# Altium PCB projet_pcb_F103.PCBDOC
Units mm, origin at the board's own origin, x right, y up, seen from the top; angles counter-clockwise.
Board outline 90.04 x 70.1 mm, 2 copper layers (TopLayer, BottomLayer); 62 components, 54 nets, 254 pads, 0 vias.
Unrouted connection lines stored in the file: 158.
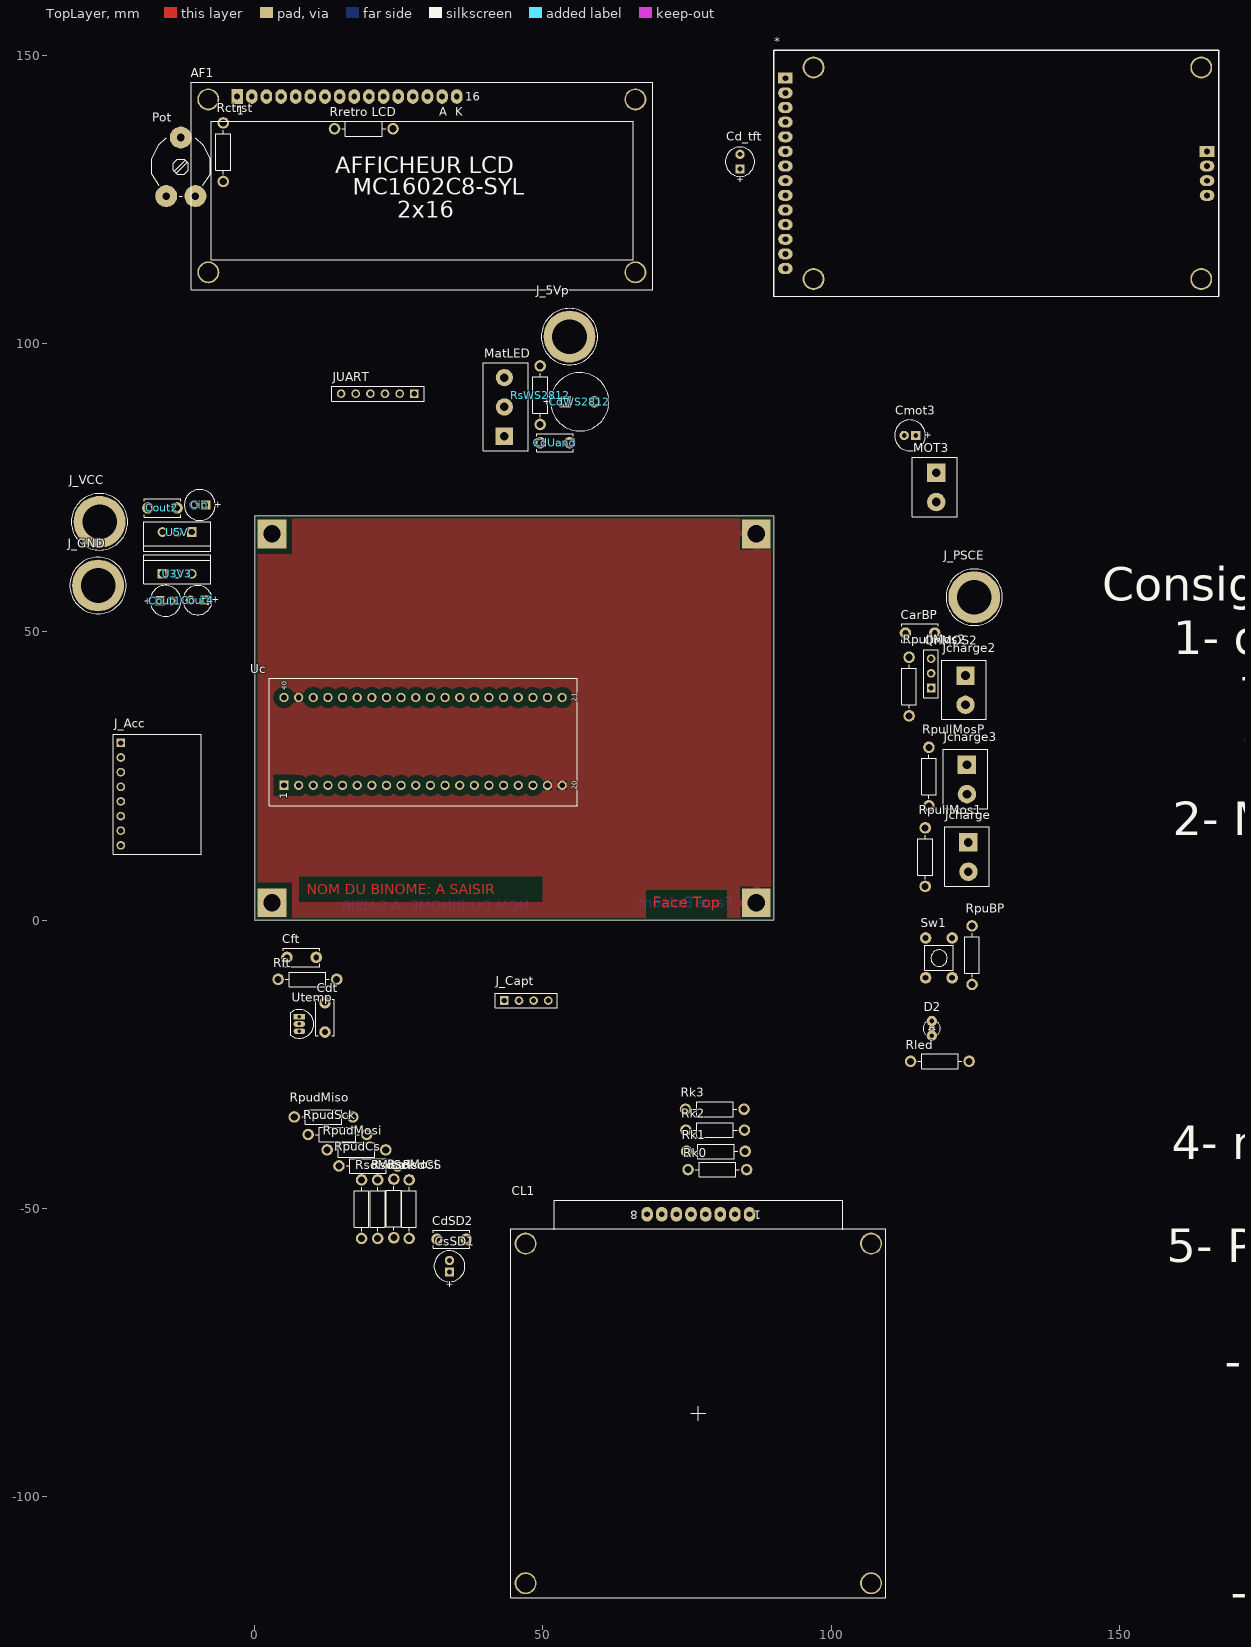
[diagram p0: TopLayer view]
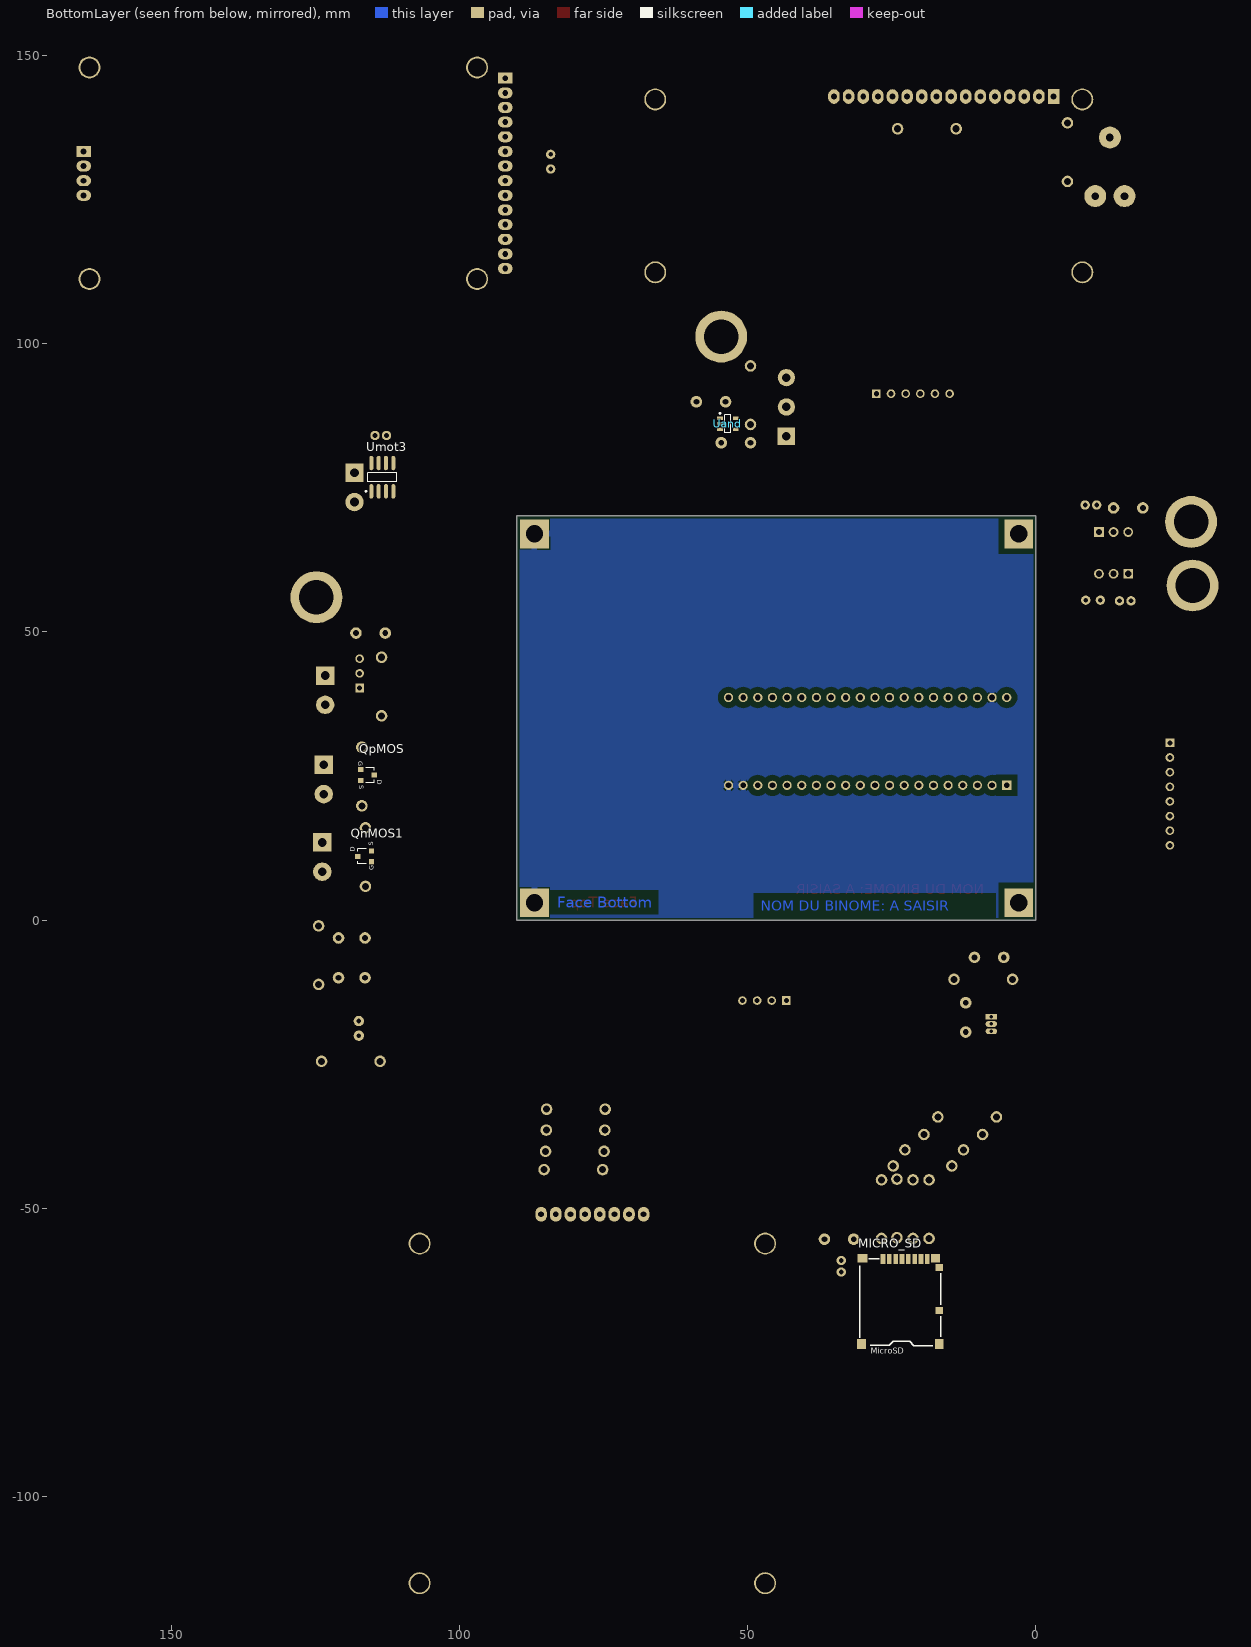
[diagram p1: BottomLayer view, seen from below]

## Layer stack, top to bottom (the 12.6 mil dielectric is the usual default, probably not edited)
TopSolder: solder mask 0.0102, Solder Resist, Dk 3.5
TopLayer: signal copper 0.0356
Dielectric1: core 0.32, FR-4, Dk 4.8
BottomLayer: signal copper 0.0356
BottomSolder: solder mask 0.0102, Solder Resist, Dk 3.5

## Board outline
0,0 0,70.104 90.043,70.104 90.043,0

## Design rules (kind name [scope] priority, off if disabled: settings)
Clearance PowerPlaneClearance [InNamedPolygon('Bot-GND') Or  InNamedPolygon('Top-GND')] p1: gap=1.016
Clearance [All] p2: gap=0.508
FabricationTestPointUsage TestPointUsage [All] p1: valid=0 allowmultiple=FALSE
FabricationTestpoint Testpoint [All] p1: side=3 testpointundercomponent=TRUE minsize=1.016 maxsize=2.54 preferedsize=1.524 minholesize=0.508 maxholesize=1.016 preferedholesize=0.813 testpointgrid=0.025 allowsidetop=TRUE allowsidebottom=TRUE usegrid=TRUE gridtolerance=0
Height [All] p1: minheight=0 maxheight=50.8 prefheight=12.7
HoleSize [All] p1: absolutevalues=TRUE maxlimit=7.62 minlimit=0.3 maxpercent=80.000 minpercent=20.000
PlaneClearance [All] p1: clearance=1.016
PlaneConnect [All] p1: planeconnectstyle=Relief reliefexpansion=0.5 reliefentries=4 reliefconductorwidth=1.016 reliefairgap=0.5
PolygonConnect [All] p1: connectstyle=Relief reliefconductorwidth=1.016 reliefentries=4 polygonreliefangle="90 Angle" airgapwidth=0.254
RoutingVias [All] p1: holewidth=0.6 width=1.524 viastyle="Through Hole" minholewidth=0.6 minwidth=1.524 maxholewidth=0.6 maxwidth=1.524
SilkToSolderMaskClearance SilkscreenOverComponentPads [IsPad] p1: minsilkscreentomaskgap=0.254 clearancetoexposedcopper=TRUE
SolderMaskExpansion [All] p1: expansion=0.051
UnpouredPolygon [All] p1: allowunpoured=FALSE
Width [All] p1: maxlimit=25.4 minlimit=0.508 preferedwidth=1.016
22 further rules are at their usual default settings.

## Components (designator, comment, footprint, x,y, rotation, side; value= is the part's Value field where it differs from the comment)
* "2.4_TFT_TOUCH" 2.4_TFT_TOUCH 90.043,108.204 r0 top
AF1 "AFFICHEUR_LCD_2X16_" AFFICHEUR_LCD_MC1602C8-SYL -3.048,142.875 r0 top
CarBP "CONDENSATEUR_CER_RAD_5.08" CONDENSATEUR_CERAMIQUE_RADIAL_5.08 112.903,49.784 r0 top
Cd_tft "10uF" CONDENSATEUR_POLARISE_ELECTROLYTIQUE_RADIAL_2.54/5.08 84.201,130.302 r90 top
CdSD2 "100nF" CONDENSATEUR_CERAMIQUE_RADIAL_5.08 31.623,-55.372 r0 top
Cdt "CONDENSATEUR_CER_RAD_5.08" CONDENSATEUR_CERAMIQUE_RADIAL_5.08 12.192,-14.351 r270 top
CdUand "CONDENSATEUR_CER_RAD_5.08" CONDENSATEUR_CERAMIQUE_RADIAL_5.08 54.61,82.804 r180 top
CdWS2812 "CONDENSATEUR_POL_ELECTROLY_RAD_5.08/10.16" CONDENSATEUR_POLARISE_ELECTROLYTIQUE_RADIAL_5.08/10.16 53.848,89.916 r0 top
Cft "CONDENSATEUR_CER_RAD_5.08" CONDENSATEUR_CERAMIQUE_RADIAL_5.08 10.668,-6.477 r180 top
Cin "CONDENSATEUR_POL_ELECTROLY_RAD_2.0/5.08" CONDENSATEUR_POLARISE_ELECTROLYTIQUE_RADIAL_2.0/5.08 -9.525,72.009 r180 top
CL1 "CLAVIER_16_TOUCHES" CLAVIER_16_TOUCHES 85.852,-51.054 r180 top
Cmot3 "10uF" CONDENSATEUR_POLARISE_ELECTROLYTIQUE_RADIAL_2.0/5.08 113.681,84.074 r180 top
Cout1 "CONDENSATEUR_POL_ELECTROLY_RAD_2.0/5.08" CONDENSATEUR_POLARISE_ELECTROLYTIQUE_RADIAL_2.0/5.08 -15.494,55.372 r0 top
Cout2 "CONDENSATEUR_CER_RAD_5.08" CONDENSATEUR_CERAMIQUE_RADIAL_5.08 -13.462,71.501 r180 top
Cout4 "CONDENSATEUR_POL_ELECTROLY_RAD_2.54/5.08" CONDENSATEUR_POLARISE_ELECTROLYTIQUE_RADIAL_2.54/5.08 -8.636,55.499 r180 top
CsSD1 "CONDENSATEUR_POL_ELECTROLY_RAD_2.0/5.08" CONDENSATEUR_POLARISE_ELECTROLYTIQUE_RADIAL_2.0/5.08 33.782,-60.071 r90 top
D2 "LED_3MM" LED_3MM 117.475,-18.796 r0 top
J_5Vp "DOUILLE BANANE 4mm" DOUILLE_BANANE_4mm#1 54.61,101.219 r0 top
J_Acc "BARRETTE_8 CONTACTS_1 RANGEE_FEMELLE_DROITE" BARRETTE_8_F_D -23.241,30.734 r270 top
J_Capt "BARRETTE_4 CONTACTS_1 RANGEE_FEMELLE_DROITE" BARRETTE_4_F_D 43.307,-13.97 r0 top
J_GND "DOUILLE BANANE 4mm" DOUILLE_BANANE_4mm#2 -27.178,58.039 r0 top
J_PSCE "DOUILLE BANANE 4mm" DOUILLE_BANANE_4mm#2 124.841,56.007 r270 top
J_VCC "DOUILLE BANANE 4mm" DOUILLE_BANANE_4mm#2 -26.924,69.088 r0 top
Jcharge "BORNIER2 DROIT A VIS" BORNIER2_A_VIS 123.825,13.462 r270 top
Jcharge2 "BORNIER2 DROIT A VIS" BORNIER2_A_VIS 123.317,42.418 r270 top
Jcharge3 "BORNIER2 DROIT A VIS" BORNIER2_A_VIS 123.571,26.924 r270 top
JUART "BARRETTE_6 CONTACTS_1 RANGEE_FEMELLE_DROITE" BARRETTE_6_F_D 27.686,91.313 r180 top
MatLED "BORNIER3 DROIT A VIS" BORNIER3_A_VIS 43.307,83.947 r90 top
MICRO_SD "MOLEX_MICRO_SD_HEADER_5027740891" MOLEX_MICRO_SD_HEADER_5027740891 26.543,-58.801 r0 bottom
MOT3 "BORNIER2 DROIT A VIS" BORNIER2_A_VIS 118.237,77.597 r270 top
Pot "RESISTANCE_VARIABLE_TRAVERSANTE : PT10LV" TRIMMER_MONOTOUR_PT10LV -15.367,125.603 r0 top
QnMOS1 "TRANSISTOR_MOSFET-N_SOT23_GSD" TRANSISTOR_MOSFET-N_SOT23_GSD 116.459,11.049 r90 bottom
QnMOS2 "TRANSISTOR_MOSFET-N_TO220_GDS" BARRETTE_3_F_D 117.348,40.259 r90 top
QpMOS "TRANSISTOR_MOSFET-P_SOT23_GSD" TRANSISTOR_MOSFET-P_SOT23_GSD 115.951,25.146 r270 bottom
Rctrst "RESISTANCE_AXIALE_1/4W" RESISTANCE_1/4W -5.461,138.303 r270 top
Rft "RESISTANCE_AXIALE_1/4W" RESISTANCE_1/4W 4.064,-10.287 r0 top
Rk0 "RESISTANCE_AXIALE_1/4W" RESISTANCE_1/4W 75.184,-43.307 r0 top
Rk1 "RESISTANCE_AXIALE_1/4W" RESISTANCE_1/4W 74.93,-40.132 r0 top
Rk2 "RESISTANCE_AXIALE_1/4W" RESISTANCE_1/4W 74.803,-36.449 r0 top
Rk3 "RESISTANCE_AXIALE_1/4W" RESISTANCE_1/4W 74.743,-32.826 r0 top
Rled "RESISTANCE_AXIALE_1/4W" RESISTANCE_1/4W 113.792,-24.511 r0 top
RpuBP "RESISTANCE_AXIALE_1/4W" RESISTANCE_1/4W 124.46,-1.016 r270 top
RpudCs "47k" RESISTANCE_1/4W 14.605,-42.672 r0 top
RpudMiso "47k" RESISTANCE_1/4W 17.018,-34.163 r180 top
RpudMosi "47k" RESISTANCE_1/4W 12.573,-39.878 r0 top
RpudSck "47k" RESISTANCE_1/4W 19.431,-37.211 r180 top
RpullMos1 "RESISTANCE_AXIALE_1/4W" RESISTANCE_1/4W 116.332,16.002 r270 top
RpullMos2 "RESISTANCE_AXIALE_1/4W" RESISTANCE_1/4W 113.538,45.593 r270 top
RpullMosP "RESISTANCE_AXIALE_1/4W" RESISTANCE_1/4W 116.967,29.972 r270 top
"Rretro LCD" "RESISTANCE_AXIALE_1/4W" RESISTANCE_1/4W 13.843,137.287 r0 top
RsdCS "22" RESISTANCE_1/4W 26.797,-45.085 r270 top
RsdMiso "22" RESISTANCE_1/4W 18.542,-45.085 r270 top
RsdMosi "22" RESISTANCE_1/4W 24.13,-44.958 r270 top
RsdSck "22" RESISTANCE_1/4W 21.336,-45.085 r270 top
RsWS2812 "220" RESISTANCE_1/4W 49.53,96.139 r270 top
Sw1 "BOUTON_POUSSOIR_MINIATURE_TRAVERSANT" BOUTON_POUSSE_PLAT_6x6 116.205,-10.414 r0 top
U3V3 "REGULATEUR_TO220_78XX" REGULATEUR_TO220_78XX -13.462,60.071 r0 top
U5V "REGULATEUR_TO220_78XX" REGULATEUR_TO220_78XX -13.462,67.31 r180 top
Uand "SN74AHCT1G08DBVR" DBV0005A_N 53.467,86.106 r180 bottom
Uc "STM32F103C8T6/PCB_DIP40" STM32F103C8T6_DIP40 5.08,23.368 r90 top
Umot3 "BD6221F-E2" SOIC8_PAS=1.27_LARG=4_LONG=5 113.411,76.835 r90 bottom
Utemp "CAPTEUR_TEMPERATURE_MCP9701-E/TO" COMPOSANT_TO92 7.747,-18.034 r180 top

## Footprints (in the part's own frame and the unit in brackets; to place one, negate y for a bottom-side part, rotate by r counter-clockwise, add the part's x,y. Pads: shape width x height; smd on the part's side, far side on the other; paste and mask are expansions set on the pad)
2.4_TFT_TOUCH [mil]
  round 150 hole 125: 0(272.44,118.11) 0(272.44,1563.78) 0(2920.47,118.11) 0(2920.47,1563.78)
  rect 100x75 hole 40: 1(80,1490) 18(2959.84,990)
  oval 100x75 hole 40: 2(80,1390) 3(80,1290) 4(80,1190) 5(80,1090) 6(80,990) 7(80,890) 8(80,790) 9(80,690) 10(80,590) 11(80,490) 12(80,390) 13(80,290) 14(80,190) 15(2959.84,690) 16(2959.84,790) 17(2959.84,890)
  silkscreen extent 0,-1 3039,1682, body extent 0,-1 3039,1681, height 650
AFFICHEUR_LCD_MC1602C8-SYL [mil] "AFFICHEUR LCD 2x16 - 80mm x 35mm"
  rect 79x100 hole 40: 1(0,0)
  oval 79x100 hole 40: 2(100,0) 3(200,0) 4(300,0) 5(400,0) 6(500,0) 7(600,0) 8(700,0) 9(800,0) 10(900,0) 11(1000,0) 12(1100,0) 13(1200,0) 14(1300,0) 15(1400,0) 16(1500,0)
  round 150 hole 126: FIX1(-196.85,-19.68) FIX2(2720.47,-19.68) FIX3(2720.47,-1200.79) FIX4(-196.85,-1200.79)
  silkscreen extent -315,-1319 2839,98, body extent -327,-1354 2843,83, height 847
BARRETTE_3_F_D [mm] "BARRETTE 3 CONTACTS ; 1 RANGEE ; DROITE ; FEMELLE ; ESPACEMENT BROCHES = 2.54 mm"
  rect 1.5x1.5 hole 0.9: 1(0,0)
  round 1.5 hole 0.9: 2(2.54,0) 3(5.08,0)
  silkscreen extent -1.7,-1.27 6.61,1.27, body extent -1.56,-1.21 6.56,1.2, height 8.5
BARRETTE_4_F_D [mm] "BARRETTE 4 CONTACTS ; 1 RANGEE ; DROITE ; FEMELLE ; ESPACEMENT BROCHES = 2.54 mm"
  rect 1.5x1.5 hole 0.9: 1(0,0)
  round 1.5 hole 0.9: 2(2.54,0) 3(5.08,0) 4(7.62,0)
  silkscreen extent -1.6,-1.27 9.2,1.27, body extent -1.53,-1.21 9.13,1.2, height 8.5
BARRETTE_6_F_D [mm] "BARRETTE 6 CONTACTS ; 1 RANGEE ; DROITE ; FEMELLE ; ESPACEMENT BROCHES = 2.54 mm"
  rect 1.5x1.5 hole 0.9: 1(0,0)
  round 1.5 hole 0.9: 2(2.54,0) 3(5.08,0) 4(7.62,0) 5(10.16,0) 6(12.7,0)
  silkscreen extent -1.7,-1.27 14.3,1.27, body extent -1.57,-1.2 14.17,1.21, height 8.5
BARRETTE_8_F_D [mm] "BARRETTE 8 CONTACTS ; 1 RANGEE ; DROITE ; FEMELLE ; ESPACEMENT BROCHES = 2.54 mm"
  rect 1.5x1.5 hole 0.9: 1(0,0)
  round 1.5 hole 0.9: 2(2.54,0) 3(5.08,0) 4(7.62,0) 5(10.16,0) 6(12.7,0) 7(15.24,0) 8(17.78,0)
  silkscreen extent -1.53,-1.27 19.3,13.97, body extent -1.53,-1.21 19.3,1.2, height 8.5
BORNIER2_A_VIS [mm] "BORNIER 2 PLOTS A VIS ; VERTICAL ; ESPACEMENT BROCHES = 5.08mm"
  rect 3.2x3.2 hole 1.5: 1(0,0)
  round 3.2 hole 1.5: 2(5.08,0)
  silkscreen extent -2.69,-4.15 7.62,3.63, body extent -2.5,-4 7.5,3.5, height 10
BORNIER3_A_VIS [mm] "BORNIER 3 PLOTS A VIS ; VERTICAL ; ESPACEMENT BROCHES = 5.08mm"
  rect 3x3 hole 1.5: 1(0,0)
  round 3 hole 1.5: 2(5.08,0) 3(10.16,0)
  silkscreen extent -2.54,-4.16 12.74,3.64, body extent -2.4,-4 12.6,3.5, height 10
BOUTON_POUSSE_PLAT_6x6 [mil] "BOUTON POUSSOIR MINIATURE ON/OFF; BOUTON PLAT/LONG ; ESPACEMENT BROCHES = 7.62mm/5.08mm"
  round 79 hole 40: 1(7.87,15.75) 2(188.98,15.75) 3(188.98,287.4) 4(7.87,287.4)
  silkscreen extent 0,67 197,236, body extent -22,-1 222,310, height 276
CLAVIER_16_TOUCHES [mil] "CLAVIER 65mm x 69mm"
  oval 79x100 hole 40: 1(0,0) 2(100,0) 3(200,0) 4(300,0) 5(400,0) 6(500,0) 7(600,0) 8(700,0)
  round 150 hole 126: FIX1(-830,2520) FIX2(1530,2520) FIX3(1530,200) FIX4(-830,200)
  silkscreen extent -930,-95 1630,2620
COMPOSANT_TO92 [mm] "BOITIER TO92 ; 3 BROCHES EN LIGNE; DIAMETRE CORPS : 4.5mm ; BROCHES : 0.51mm x 0.48mm"
  rect 2x1 hole 0.6: 1(0,-1.27)
  oval 2x1 hole 0.6: 2(0,0) 3(0,1.27)
  silkscreen extent -2.48,-2.48 1.5,2.48, body extent -2.43,-2.4 1.5,2.4, height 6
CONDENSATEUR_CERAMIQUE_RADIAL_5.08 [mil] "CONDENSATEUR TRAVERSANT CERAMIQUE RADIAL ; DIMENSIONS : 3.17mm x 5.08mm"
  round 79 hole 40: 1(0,0) 2(200,0)
  silkscreen extent -25,-62 225,62, body extent -11,-43 209,42, height 148
CONDENSATEUR_POLARISE_ELECTROLYTIQUE_RADIAL_2.0/5.08 [mil] "CONDENSATEUR POLARISE ELECTROLYTIQUE RADIAL ; DIAMETRE : 5.08mm ; ESPACEMENT BROCHES : 2mm"
  rect 64x64 / inner round 64 / far side round 64 hole 32: 1(-39.37,0)
  round 64 hole 32: 2(39.37,0)
  silkscreen extent -106,-106 105,106, body extent -98,-98 98,98, height 433
CONDENSATEUR_POLARISE_ELECTROLYTIQUE_RADIAL_2.54/5.08 [mil] "CONDENSATEUR_POLARISE_ELECTROLYTIQUE_RADIAL ; DIAMETRE : 5.08mm ; ESPACEMENT BROCHES : 2.54mm"
  rect 64x64 / inner round 64 / far side round 64 hole 32: 1(0,0)
  round 64 hole 32: 2(100,0)
  silkscreen extent -50,-100 150,100, body extent -50,-101 149,98, height 446
CONDENSATEUR_POLARISE_ELECTROLYTIQUE_RADIAL_5.08/10.16 [mil] "CONDENSATEUR POLARISE ELECTROLYTIQUE RADIAL ; DIAMETRE : 10.16mm ; ESPACEMENT BROCHES : 5.08mm"
  rect 79x79 / inner round 79 / far side round 79 hole 40: 1(0,0)
  round 79 hole 40: 2(200,0)
  silkscreen extent -98,-199 299,198, body extent -98,-197 295,197, height 630
DBV0005A_N [mm] "SOT23, 5-Leads, Body 3.05x1.75mm, Pitch 0.95mm, IPC Medium Density"
  rect 1x0.6 smd: 1(-1.375,0.95) 2(-1.375,0) 3(-1.375,-0.95) 4(1.375,-0.95) 5(1.375,0.95)
  silkscreen extent -1.5,-1.55 0.5,1.92, body extent -1.42,-1.46 1.42,1.46, height 1.08
DOUILLE_BANANE_4mm#1 [mm] "DOUILLE BANANE ; DIAMETRE PASSAGE CONTACT = 4 mm ; DIAMETRE PERCAGE = 6 mm"
  round 9 hole 6: 1(0,0)
  TopLayer pour cut-out: -5.55,2.35 -4.2,4.3 -2.3,5.6 0,6 2.3,5.6 4.2,4.3 5.55,2.35 6,0 5.55,-2.35 4.3,-4.25 2.35,-5.55 0,-6 -2.35,-5.55 -4.2,-4.3 -5.55,-2.35 -6,0
  BottomLayer pour cut-out: -5.55,2.35 -4.2,4.3 -2.3,5.6 0,6 2.3,5.6 4.2,4.3 5.55,2.35 6,0 5.55,-2.35 4.3,-4.25 2.35,-5.55 0,-6 -2.35,-5.55 -4.2,-4.3 -5.55,-2.35 -6,0
  silkscreen extent -4.89,-4.89 4.89,4.89, body extent -5.5,-5.6 5.63,5.53, height 4.79
DOUILLE_BANANE_4mm#2 [mm] "DOUILLE BANANE ; DIAMETRE PASSAGE CONTACT = 4 mm ; DIAMETRE PERCAGE = 6 mm"
  round 9 hole 6: 1(0,0)
  silkscreen extent -4.89,-4.89 4.89,4.89, body extent -5.5,-5.6 5.63,5.53, height 4.79
LED_3MM [mm] "LED 3mm; 2 Leads"
  round 1.8 hole 0.8: 1(0,-1.27) 2(0,1.27)
  silkscreen extent -1.5,-1.06 1.5,1.06, body extent -1.64,-1.65 1.65,1.65, height 5.51
MOLEX_MICRO_SD_HEADER_5027740891 [mm]
  rect 1.5x1.7 smd: 0(-9.754,14.783) 0(3.74,14.783)
  rect 1.5x1.5 smd: 0(-9.1,-0.1)
  rect 1.7x1.5 smd: 0(3.55,-0.1)
  rect 0.8x1.68 smd: 1(0,0) 2(-1.1,0) 3(-2.2,0) 4(-3.3,0) 5(-4.4,0) 6(-5.5,0) 7(-6.6,0) 8(-7.7,0)
  rect 1.3x1.2 smd: 9(-9.75,1.49) 10(-9.75,8.94)
  round 1.524 on Bottom Overlay: ""(0.432,1.93)
  silkscreen extent -10.01,0 4.04,15.04, body extent -10.1,-0.68 4.2,15.32, height 1.88
REGULATEUR_TO220_78XX [mm] "BOITIER TO220 ; DIMENSIONS : 11.2mm x 4.7mm ; ESPACEMENT BROCHES : 2.54 mm"
  rect 1.7x1.7 hole 1.1: 1(-2.54,0)
  round 1.7 hole 1.1: 2(0,0) 3(2.54,0)
  silkscreen extent -5.83,-1.77 5.8,3.29, body extent -5.61,-1.59 5.61,3.1, height 19.33
RESISTANCE_1/4W [mil] "RESISTANCE 0.25W; DIAMETRE : 2.54mm ; LONGUEUR : 6.35mm ; PAS : 10.16mm"
  round 79 hole 48: 1(0,0) 2(400,0)
  silkscreen extent 50,-50 350,50, body extent -15,-47 409,44, height 116
SOIC8_PAS=1.27_LARG=4_LONG=5 [mm] "Small Outline Integrated Circuit ; 8 Leads ; Body Width = 4 mm ; Pitch = 1.27 mm ; IPC Low Density"
  oval 2.5x0.7 smd: 1(-2.45,1.905) 2(-2.45,0.635) 3(-2.45,-0.635) 4(-2.45,-1.905) 5(2.45,-1.905) 6(2.45,-0.635) 7(2.45,0.635) 8(2.45,1.905)
  silkscreen extent -2.57,-2.5 0.8,2.93, body extent -3.01,-2.5 3,2.5, height 1.75
STM32F103C8T6_DIP40 [mm] "STM32F103 monté sur DIP40"
  rect 1.6x1.6 hole 1: 1(0,0)
  round 1.6 hole 1: 2(0,-2.54) 3(0,-5.08) 4(0,-7.62) 5(0,-10.16) 6(0,-12.7) 7(0,-15.24) 8(0,-17.78) 9(0,-20.32) 10(0,-22.86) 11(0,-25.4) 12(0,-27.94) 13(0,-30.48) 14(0,-33.02) 15(0,-35.56) 16(0,-38.1) 17(0,-40.64) 18(0,-43.18) 19(0,-45.72) 20(0,-48.26) 21(15.24,-48.26) 22(15.24,-45.72) 23(15.24,-43.18) 24(15.24,-40.64) 25(15.24,-38.1) 26(15.24,-35.56) 27(15.24,-33.02) 28(15.24,-30.48) 29(15.24,-27.94) 30(15.24,-25.4) 31(15.24,-22.86) 32(15.24,-20.32) 33(15.24,-17.78) 34(15.24,-15.24) 35(15.24,-12.7) 36(15.24,-10.16) 37(15.24,-7.62) 38(15.24,-5.08) 39(15.24,-2.54) 40(15.24,0)
  silkscreen extent -3.56,-50.92 18.54,2.54, body extent -3.63,-51.04 18.37,6.1, height 20.63
TRANSISTOR_MOSFET-N_SOT23_GSD [mm] "SOT23 ; DIMENSIONS : 3.0mm x 2.5 mm"
  rect 0.9x0.95 smd: 1(-0.95,-1.175) 2(0.95,-1.175) 3(0,1.175)
  silkscreen extent -1.3,-0.3 1.3,1.18, body extent -1.5,-1.57 1.5,1.57, height 1.1
TRANSISTOR_MOSFET-P_SOT23_GSD [mm] "SOT23 ; DIMENSIONS : 3.0mm x 2.5 mm"
  rect 0.9x0.95 smd: 1(-0.95,-1.175) 2(0.95,-1.175) 3(0,1.175)
  silkscreen extent -1.3,-0.3 1.3,1.18, body extent -1.5,-1.57 1.5,1.57, height 1.1
TRIMMER_MONOTOUR_PT10LV [mil] "RESISTANCE VARIABLE MONOTOUR  PT10LV; DIMENSIONS : 10.16mm x 5.08mm"
  round 150 hole 52: 1(0,0) 2(100,400) 3(200,0)
  silkscreen extent -100,0 300,400, body extent -102,-9 303,408, height 246

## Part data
AF1: library part AFFICHEUR_LCD_MC1602C8-SYL, "AFFICHEUR LCD - 2x16 LIGNES - 5X7 DOTS - STN - 80mm x 36mm"
CarBP Cdt CdUand Cft Cout2: "CONDENSATEUR TRAVERSANT CERAMIQUE RADIAL 5.08mm"
Cd_tft CdSD2 Cmot3: library part Condensateur, "Capacitor"
CdWS2812: "CONDENSATEUR POLARISE ELECTROLYTIQUE RADIAL 5.08/10.16"
Cin Cout1 CsSD1: "CONDENSATEUR POLARISE ELECTROLYTIQUE RADIAL 2.0/5.08"
CL1: "CLAVIER 16 TOUCHES"
Cout4: "CONDENSATEUR POLARISE ELECTROLYTIQUE RADIAL 2.54/5.08"
D2: "LED 3MM - ROUGE/VERTE/JAUNE"
J_5Vp J_GND J_PSCE J_VCC: library part DOUILLE_BANANE_4mm, "DOUILLE BANANE 4 mm"
J_Capt: "BARRETTE 4 CONTACTS 1 RANGEE FEMELLE DROITE"
Jcharge Jcharge2 Jcharge3 MOT3: library part "BORNIER2_DROIT_A VIS", "BORNIER 2 PLOTS DROIT A VIS 5.08mm"
JUART: "BARRETTE 6 CONTACTS 1 RANGEE FEMELLE DROITE"
MatLED: library part "BORNIER3_DROIT_A VIS", "BORNIER 3 PLOTS DROIT A VIS 5.08mm"
Pot: "RESISTANCE VARIABLE_TRAVERSANTE : PT10LV"
QnMOS1: "TRANSISTOR MOSFET CANAL N BOITIER SOT23_GSD"
QnMOS2: "TRANSISTOR MOSFET CANAL N BOITIER TO220_GDS"
QpMOS: "TRANSISTOR MOSFET CANAL P BOITIER SOT23_GSD"
Rctrst Rft Rk0 Rk1 Rk2 Rk3 Rled RpuBP RpullMos1 RpullMos2 RpullMosP "Rretro LCD": "RESISTANCE TRAVERSANTE AXIALE 1/4W"
RpudCs RpudMiso RpudMosi RpudSck RsdCS RsdMiso RsdMosi RsdSck RsWS2812: library part Resistor, "Resistor"
Sw1: "BOUTON POUSSOIR MINIATURE TRAVERSANT ON/OFF"
U3V3 U5V: "REGULATEUR DE TENSION POSITIVE 78XX BOITIER TO220"
Uand: "Single 2-Input Positive-AND Gate, DBV0005A, LARGE T&R"
Uc: "MICROCONTROLEUR 32 BITS - 72MHz - 34 I/O - 64 KO : FLASH - 20KO RAM - 10 CANAUX A/D 12 BITS - DIP40 - UART, SPI, I2C, USB, CAN"
Umot3: library part BD6220F, "H Bridge - 2A"
Utemp: "CAPTEUR DE TEMPERATURE ANALOGIQUE LINEAIRE - TO92"

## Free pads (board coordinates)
  rect 5x5 hole 3: 1(3,67) 2(3,3) 3(87,3) 4(87,67)

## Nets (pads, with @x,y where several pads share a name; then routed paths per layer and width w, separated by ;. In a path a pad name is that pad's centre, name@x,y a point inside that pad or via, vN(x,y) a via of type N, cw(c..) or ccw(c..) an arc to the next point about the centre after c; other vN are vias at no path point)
+3V3: *.1 *.8 Cd_tft.1 CdSD2.2 Cout4.1 CsSD1.1 Jcharge.1 MICRO_SD.4 QpMOS.2 RpudCs.1 RpudMiso.2 RpudMosi.1 RpudSck.2 RpullMosP.2 U3V3.3
+3V3_BP: Rk0.2 Rk1.2 Rk2.2 Rk3.2 RpuBP.1 Uc.40
+5V: "Rretro LCD.1" AF1.2 Cdt.1 CdUand.2 Cout1.1 Cout2.2 J_Capt.1 JUART.2 Rctrst.1 U3V3.1 U5V.3 Uand.5 Uc.38 Utemp.1
+5VP: CdWS2812.1 J_5Vp.1 MatLED.2
+12V: J_PSCE.1 Jcharge2.1
GND: *.2 AF1.1 AF1.16 CarBP.1 Cd_tft.2 CdSD2.1 Cdt.2 CdUand.1 CdWS2812.2 Cft.2 Cin.2 Cmot3.1 Cout1.2 Cout2.1 Cout4.2 CsSD1.2 D2.2 J_Acc.2 J_Capt.4 J_GND.1 Jcharge3.2 JUART.3 MatLED.1 MICRO_SD.0 MICRO_SD.6 MICRO_SD.9 pad.3 pad.4 Pot.3 QnMOS1.2 QnMOS2.3 RpullMos1.1 RpullMos2.1 Sw1.1 U3V3.2 U5V.2 Uand.3 Uc.19 Uc.20 Uc.39 Umot3.8 Utemp.3
MOT3_1: MOT3.2 Umot3.1
MOT3_2: MOT3.1 Umot3.7
NetAF1_15: "Rretro LCD.2" AF1.15
NetD2_1: D2.1 Rled.2
NetJcharge2_2: Jcharge2.2 QnMOS2.2
NetJcharge3_1: Jcharge3.1 QpMOS.3
NetJcharge_2: Jcharge.2 QnMOS1.3
NetMatLED_3: MatLED.3 RsWS2812.1
NetMICRO_SD_2: MICRO_SD.2 RsdCS.2
NetMICRO_SD_3: MICRO_SD.3 RsdMosi.2
NetMICRO_SD_5: MICRO_SD.5 RsdSck.2
NetMICRO_SD_7: MICRO_SD.7 RsdMiso.2
NetPot_1: Pot.1 Rctrst.2
NetRft_1: Rft.1 Utemp.2
NetRsWS2812_2: RsWS2812.2 Uand.4
PA0_AN0: J_Acc.1 Uc.5
PA1_AN1: Cft.1 Rft.2 Uc.6
PA2_U2TX: JUART.5 Uc.7
PA3_U2RX: JUART.4 Uc.8
PA4_KEYBI0: CL1.5 Rk0.1 Uc.9
PA5_KEYBI1: *.7 *.10 CL1.6 Rk1.1 RpudSck.1 RsdSck.1 Uc.10
PA6_KEYBI2: *.9 *.13 CL1.7 Rk2.1 RpudMiso.1 RsdMiso.1 Uc.11
PA7_KEYBI3: *.6 *.12 CL1.8 Rk3.1 RpudMosi.2 RsdMosi.1 Uc.12
PA8_KEYBO0: *.5 CL1.1 Uc.25
PA9_KEYBO1: *.4 CL1.2 Uc.26
PA10_KEYBO2: CL1.3 Uc.27 Umot3.4
PA11_KEYBO3: *.11 CL1.4 Uc.28
PA12_OUT: *.3 J_Capt.2 Uc.29
PA15_LED: Rled.1 Uc.30
PB0_AN8: J_Capt.3 Uc.13
PB1_AN9: Uc.14
PB3: *.14 Uc.31
PB4: AF1.5 Uc.32
PB5: AF1.6 Uc.33
PB6_U1TX: Uc.34
PB7_U1RX: Uc.35
PB8_I2C_SCL: AF1.4 J_Acc.3 Uc.36
PB9_I2C_SDA: AF1.11 J_Acc.4 Uc.37
PB10_LCD_D5: AF1.12 RpudCs.2 RsdCS.1 Uc.15
PB11_LCD_D6: AF1.13 Uc.16
PB12_BUTTON: AF1.14 CarBP.2 RpuBP.2 Sw1.2 Uc.21
PB13_LEDS_WS2812: QpMOS.1 RpullMosP.1 Uand.1 Uand.2 Uc.22
PB14_NMOS1: QnMOS1.1 RpullMos1.2 Uc.23
PB15_NMOS2: QnMOS2.1 RpullMos2.2 Uc.24 Umot3.5
PC14_OSC32: Uc.3
PC15_OSC32: Uc.4
VCC: Cin.1 Cmot3.2 J_VCC.1 U5V.1 Umot3.2 Umot3.3 Umot3.6
VCONTRAST: AF1.3 Pot.2
pads on no net: *.0 *.15 *.16 *.17 *.18 AF1.7 AF1.8 AF1.9 AF1.10 AF1.FIX1 AF1.FIX2 AF1.FIX3 AF1.FIX4 CL1.FIX1 CL1.FIX2 CL1.FIX3 CL1.FIX4 J_Acc.5 J_Acc.6 J_Acc.7 J_Acc.8 JUART.1 JUART.6 MICRO_SD. MICRO_SD.1 MICRO_SD.8 MICRO_SD.10 Sw1.3 Sw1.4 Uc.1 Uc.2 Uc.17 Uc.18

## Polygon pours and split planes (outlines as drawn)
GND on BottomLayer "Bot-GND" (solid, pour order 5): 0.508,69.596 89.535,69.596 89.535,0.381 0.508,0.381
GND on TopLayer "Top-GND" (solid, pour order 4): 0.508,69.596 89.535,69.596 89.535,0.381 0.508,0.381

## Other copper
TopLayer:
  text "NOM DU BINOME: A SAISIR" at 9.017,4.445 h1.8
  text "Face Top" at 69.088,2.159 h1.91
BottomLayer:
  text "Face Bottom" at 83.058,2.159 h1.91
  text "NOM DU BINOME: A SAISIR" at 47.752,1.651 h1.8

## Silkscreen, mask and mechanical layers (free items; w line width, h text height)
TopOverlay:
  text "Consignes / Conseils :" at 147.066,53.467 h10
  text "1- désactivez la fonctionnalité \"online DRC\"" at 159.385,44.196 h10
  text "Tools->Preferences -> décocher 'online DRC'" at 171.45,34.417 h10
  text "Tools->Reset error markers" at 171.831,23.622 h10
  text "2- Masquez les plans de masse" at 159.258,12.827 h10
  text "Tools->Polygon Pours -> Shelve 2 polygons" at 171.958,3.048 h10
  text "(penser à les réafficher et le re-générer lorsque le routage est terminé !)" at 171.704,-6.985 h10
  text "3- Si elles sont visibles / gênantes : masquez les couches mécaniques 3D" at 159.258,-18.288 h10
  text "Bouton-droit sur les onglets (en bas) Mechanical1, 13 -> Hide" at 173.228,-29.591 h10
  text "4- mettre vos noms à la place de \"nom du binôme\"" at 159.131,-43.434 h10
  text "5- Par défaut, la taille de piste minimale est définie à 20 mils.  /     Si cela s'avère absolutement nécessaire, vous pouvez modifier ce réglage dans /     -> Design -> Rules -> Routing -> Width -> Width" at 158.242,-81.28 h10
  text "6- Par défaut, la clearance (espace minimale entre deux objets dont le net diffère) est reglée à 20 mils. /     Si cela s'avère nécessaire (petit composant CMS / volonté assumée d'une règle moins stricte), /      vous pouvez descendre à 10mils : /     -> Design -> Rules -> Electrical -> Clearance-> Clearance" at 159.258,-121.412 h10
  text "7- supprimez ces consignes si elles vous gênent" at 159.639,-132.08 h10
Mechanical15:
  the board outline again, w0.508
